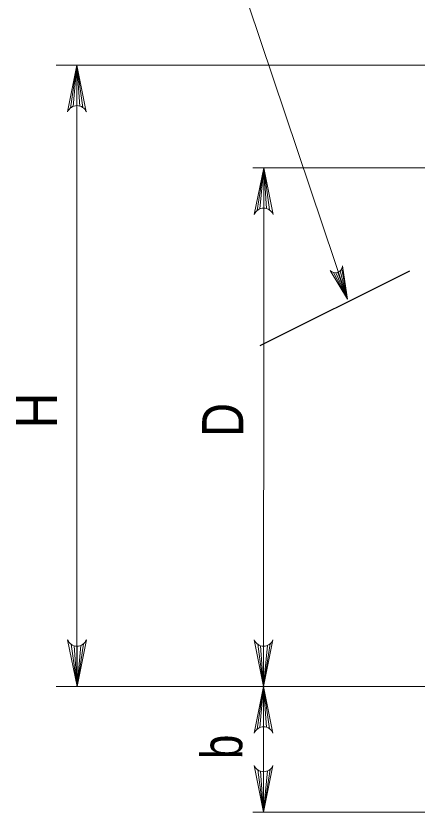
# Model space of a CAD drawing. Extents: x 1083.1 to 1117.1, y 697.4 to 743.4.
# Drawn here: x 1108.316 to 1109.836, y 724.626 to 727.648 of the extents above; entities that cross this region are included whole.
import ezdxf

# ---------------------------------------------------------------- set-up
doc = ezdxf.new("R2010")
doc.units = 0
doc.header["$LTSCALE"] = 0.064
doc.layers.add('1', color=7, linetype='Continuous', lineweight=13)

msp = doc.modelspace()

# ---------------------------------------------------------------- linework, layer by layer
at = {"layer": '1'}
for p, q in [((1108.46833, 727.46058), (1110.567, 727.46058)), ((1108.52225, 727.2985), (1108.547, 727.46058)), ((1108.53267, 727.30458), (1108.547, 727.46058)), ((1108.547, 727.30742), (1108.547, 727.46058)), ((1108.55833, 727.30575), (1108.547, 727.46058)), ((1108.56942, 727.30033), (1108.547, 727.46058)), ((1108.547, 725.103), (1108.547, 727.46058)), ((1110.67108, 727.07175), (1109.213, 727.07175)), ((1109.22975, 726.90967), (1109.25458, 727.07183)), ((1109.24017, 726.91583), (1109.25458, 727.07183)), ((1109.2545, 724.62625), (1109.25458, 727.07183)), ((1109.25458, 726.91867), (1109.25458, 727.07183)), ((1109.26592, 726.917), (1109.25458, 727.07183)), ((1109.277, 726.91158), (1109.25458, 727.07183)), ((1109.51942, 726.67417), (1109.5725, 726.57308)), ((1109.528, 726.67317), (1109.5725, 726.57308)), ((1109.536, 726.67475), (1109.5725, 726.57308)), ((1109.54492, 726.68017), (1109.5725, 726.57308)), ((1109.55025, 726.68667), (1109.5725, 726.57308)), ((1108.52467, 725.26308), (1108.54708, 725.10283)), ((1108.53575, 725.25767), (1108.54708, 725.10283)), ((1108.57192, 725.265), (1108.54708, 725.10283)), ((1108.5615, 725.25883), (1108.54708, 725.10283)), ((1108.54708, 725.256), (1108.54708, 725.10283)), ((1109.23208, 725.26308), (1109.2545, 725.10283)), ((1109.24317, 725.25767), (1109.2545, 725.10283)), ((1109.27925, 725.265), (1109.2545, 725.10283)), ((1109.26892, 725.25883), (1109.2545, 725.10283)), ((1109.2545, 725.256), (1109.2545, 725.10283)), ((1108.46833, 725.103), (1110.21792, 725.10275)), ((1109.22967, 724.94075), (1109.2545, 725.10283)), ((1109.24008, 724.94683), (1109.2545, 725.10283)), ((1109.2545, 724.94967), (1109.2545, 725.10283)), ((1109.26583, 724.94808), (1109.2545, 725.10283)), ((1109.27692, 724.94258), (1109.2545, 725.10283)), ((1109.23208, 724.7865), (1109.2545, 724.62625)), ((1109.24317, 724.78108), (1109.2545, 724.62625)), ((1109.27925, 724.78842), (1109.2545, 724.62625)), ((1109.26883, 724.78225), (1109.2545, 724.62625)), ((1109.2545, 724.77942), (1109.2545, 724.62625)), ((1110.671, 724.62633), (1109.213, 724.62633))]:
    msp.add_line(p, q, dxfattribs=at)
at = {"layer": '1', "lineweight": 25}
msp.add_line((1109.24075, 726.39658), (1109.80908, 726.68067), dxfattribs=at)
at = {"layer": '1'}
for points in [[(1109.5725, 726.57308), (1108.584, 729.51567), (1108.82758, 729.51567)], [(1108.51158, 727.28358), (1108.547, 727.46058), (1108.58242, 727.28358)], [(1109.21917, 726.89483), (1109.25458, 727.07183), (1109.29, 726.89483)], [(1109.55392, 726.699), (1109.5725, 726.57308), (1109.50675, 726.68208)], [(1108.5825, 725.27983), (1108.54708, 725.10283), (1108.51167, 725.27983)], [(1109.28992, 725.27983), (1109.2545, 725.10283), (1109.21908, 725.27983)], [(1109.21908, 724.92583), (1109.2545, 725.10283), (1109.28992, 724.92583)], [(1109.28983, 724.80325), (1109.2545, 724.62625), (1109.21908, 724.80325)]]:
    msp.add_lwpolyline(points, dxfattribs=at)
for centre, start, end in [((1108.54706, 727.2693), 22.08782, 157.91395), ((1109.25461, 726.88053), 22.08782, 157.91395), ((1108.54707, 725.29416), 202.08782, 337.91395), ((1109.25445, 725.29416), 202.08782, 337.91395), ((1109.25453, 724.91157), 22.08782, 157.91395), ((1109.25443, 724.81757), 202.08782, 337.91395)]:
    msp.add_arc(centre, 0.0382, start, end, dxfattribs=at)
msp.add_ellipse((1109.52685, 726.70017), major_axis=(-0.02556, 0.00859), ratio=0.999895, start_param=1.0543275, end_param=3.4249407, dxfattribs=at)

# ---------------------------------------------------------------- texts
for s, width, p in [('H', 0.9, (1108.47167, 726.083)), ('D', 0.85, (1109.17725, 726.05092)), ('b', 0.8, (1109.17342, 724.8275))]:
    msp.add_text(s, height=0.156, rotation=90, dxfattribs=dict(at, width=width)).set_placement(p)

doc.saveas('drawing.dxf')
